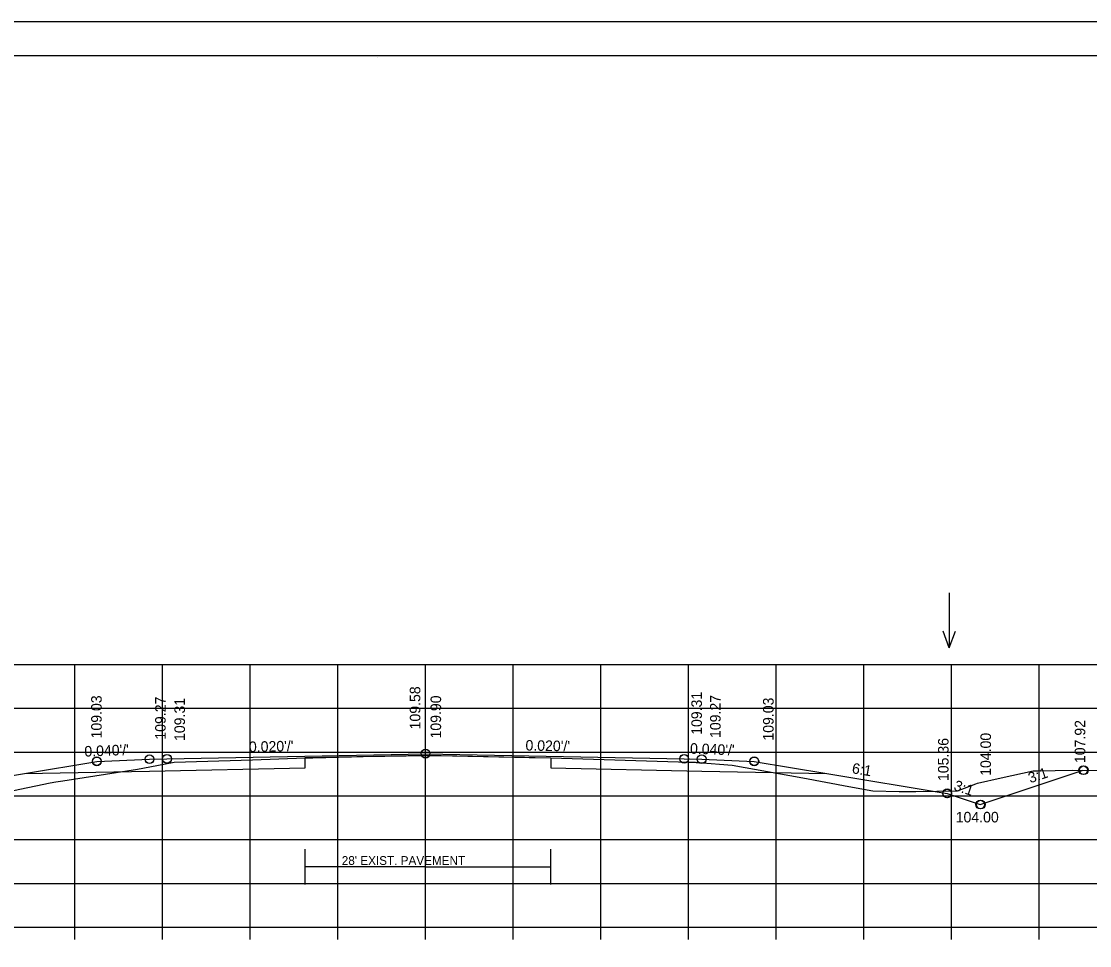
# Model space of a CAD drawing. Extents: x 1175611 to 1176402, y -433344 to -416213.
# Drawn here: x 1175734.9 to 1175856.7, y -433235.6 to -433130.2 of the extents above; entities that cross this region are included whole.
import ezdxf

# ---------------------------------------------------------------- set-up
doc = ezdxf.new("R2010")
doc.units = 0
for name, color, linetype in [('R_Alt Surface', 7, 'Continuous'), ('R_Axis', 7, 'Continuous'), ('R_Border', 7, 'Continuous'), ('R_Draft', 7, 'Continuous'), ('R_Exist Surface', 7, 'Continuous'), ('R_Fin Surface', 7, 'Continuous'), ('R_Grid', 7, 'Continuous'), ('R_No Plot', 7, 'Continuous'), ('R_Water Annot', 7, 'Continuous'), ('R_Xsect Elev', 7, 'Continuous'), ('R_Xsect Slope', 7, 'Continuous')]:
    doc.layers.add(name, color=color, linetype=linetype)

msp = doc.modelspace()

# ---------------------------------------------------------------- linework, layer by layer
at = {"layer": 'R_Alt Surface'}
msp.add_lwpolyline([(1175735.2, -433216), (1175749.47, -433215.72), (1175767.25, -433215.36), (1175767.25, -433214.19), (1175780.97, -433213.92), (1175795.26, -433214.21), (1175795.26, -433215.37), (1175812.47, -433215.72), (1175826.75, -433216)], dxfattribs=at)
at = {"layer": 'R_Axis'}
for p, q in [((1175640.97, -433233.55), (1175920.97, -433233.55)), ((1175740.97, -433234.95), (1175740.97, -433233.55)), ((1175750.97, -433234.95), (1175750.97, -433233.55)), ((1175760.97, -433234.95), (1175760.97, -433233.55)), ((1175770.97, -433234.95), (1175770.97, -433233.55)), ((1175780.97, -433234.95), (1175780.97, -433233.55)), ((1175790.97, -433234.95), (1175790.97, -433233.55)), ((1175800.97, -433234.95), (1175800.97, -433233.55)), ((1175810.97, -433234.95), (1175810.97, -433233.55)), ((1175820.97, -433234.95), (1175820.97, -433233.55)), ((1175830.97, -433234.95), (1175830.97, -433233.55)), ((1175840.97, -433234.95), (1175840.97, -433233.55)), ((1175850.97, -433234.95), (1175850.97, -433233.55))]:
    msp.add_line(p, q, dxfattribs=at)
at = {"layer": 'R_Border'}
for p, q in [((1175622.97, -433134.09), (1175939.15, -433134.09)), ((1175775.49, -433134.35), (1175775.49, -433134.35)), ((1175775.49, -433134.35), (1175775.49, -433134.35))]:
    msp.add_line(p, q, dxfattribs=at)
at = {"layer": 'R_Draft'}
for q in [(1175767.25, -433226.65), (1175795.26, -433226.65)]:
    msp.add_line((1175780.9, -433226.65), q, dxfattribs=at)
for points in [[(1175767.25, -433228.65), (1175767.25, -433224.65)], [(1175795.26, -433228.65), (1175795.26, -433224.65)]]:
    msp.add_lwpolyline(points, dxfattribs=at)
at = {"layer": 'R_Exist Surface'}
msp.add_lwpolyline([(1175729.72, -433218.82), (1175738.16, -433217.08), (1175738.78, -433216.96), (1175739.58, -433216.83), (1175748.11, -433215.51), (1175749.53, -433215.25), (1175752.27, -433214.72), (1175761.21, -433214.43), (1175767.25, -433214.22), (1175768.12, -433214.2), (1175772.5, -433214.09), (1175773.84, -433214.07), (1175781.24, -433213.96), (1175781.35, -433213.96), (1175781.45, -433213.96), (1175781.86, -433213.95), (1175782.27, -433213.96), (1175791.13, -433214.13), (1175792.25, -433214.15), (1175792.79, -433214.16), (1175795.26, -433214.23), (1175811.04, -433214.71), (1175811.4, -433214.72), (1175811.73, -433214.72), (1175811.85, -433214.74), (1175812.1, -433214.75), (1175815.94, -433215.05), (1175819.96, -433215.76), (1175824.01, -433216.48), (1175829.26, -433217.48), (1175832.01, -433217.99), (1175835.01, -433218.05), (1175836.39, -433218.07), (1175836.89, -433218.07), (1175841.65, -433217.97), (1175843.73, -433217.19), (1175843.92, -433217.11), (1175846.65, -433216.51), (1175850.3, -433215.71), (1175850.82, -433215.69), (1175854.78, -433215.62), (1175862.52, -433215.68)], dxfattribs=at)
at = {"layer": 'R_Fin Surface'}
msp.add_lwpolyline([(1175709.02, -433216.06), (1175718.59, -433219.25), (1175721.47, -433218.29), (1175735.2, -433216), (1175743.47, -433214.62), (1175749.47, -433214.38), (1175751.47, -433214.34), (1175780.97, -433213.75), (1175810.47, -433214.34), (1175812.47, -433214.38), (1175818.47, -433214.62), (1175826.75, -433216), (1175840.47, -433218.29), (1175844.24, -433219.55), (1175855.98, -433215.63)], dxfattribs=at)
msp.add_lwpolyline([(1175709.02, -433216.06), (1175718.59, -433219.25), (1175721.47, -433218.29), (1175735.2, -433216), (1175743.47, -433214.62), (1175749.47, -433214.38), (1175751.47, -433214.34), (1175780.97, -433213.75), (1175810.47, -433214.34), (1175812.47, -433214.38), (1175818.47, -433214.62), (1175826.75, -433216), (1175840.47, -433218.29), (1175844.24, -433219.55), (1175855.98, -433215.63)], dxfattribs=at)
at = {"layer": 'R_Grid'}
for p, q in [((1175640.97, -433203.55), (1175920.97, -433203.55)), ((1175740.97, -433233.55), (1175740.97, -433203.55)), ((1175750.97, -433233.55), (1175750.97, -433203.55)), ((1175760.97, -433233.55), (1175760.97, -433203.55)), ((1175770.97, -433233.55), (1175770.97, -433203.55)), ((1175780.97, -433233.55), (1175780.97, -433203.55)), ((1175790.97, -433233.55), (1175790.97, -433203.55)), ((1175800.97, -433233.55), (1175800.97, -433203.55)), ((1175810.97, -433233.55), (1175810.97, -433203.55)), ((1175820.97, -433233.55), (1175820.97, -433203.55)), ((1175830.97, -433233.55), (1175830.97, -433203.55)), ((1175840.97, -433233.55), (1175840.97, -433203.55)), ((1175850.97, -433233.55), (1175850.97, -433203.55)), ((1175640.97, -433208.55), (1175920.97, -433208.55)), ((1175640.97, -433213.55), (1175920.97, -433213.55)), ((1175640.97, -433218.55), (1175920.97, -433218.55)), ((1175640.97, -433223.55), (1175920.97, -433223.55)), ((1175640.97, -433228.55), (1175920.97, -433228.55)), ((1175640.97, -433233.55), (1175920.97, -433233.55))]:
    msp.add_line(p, q, dxfattribs=at)
at = {"layer": 'R_No Plot'}
msp.add_line((1175610.57, -433130.2), (1175943.91, -433130.2), dxfattribs=at)
msp.add_lwpolyline([(1175610.57, -433130.2), (1175943.91, -433130.2), (1175943.91, -433343.53), (1175610.57, -433343.53)], close=True, dxfattribs=at)
for centre in [(1175743.47, -433214.6), (1175743.47, -433214.62), (1175749.47, -433214.36), (1175749.47, -433214.38), (1175751.47, -433214.32), (1175751.47, -433214.34), (1175780.97, -433213.73), (1175780.97, -433213.75), (1175810.47, -433214.32), (1175810.47, -433214.34), (1175812.47, -433214.36), (1175812.47, -433214.38), (1175818.47, -433214.6), (1175818.47, -433214.62), (1175855.98, -433215.63), (1175855.98, -433215.63), (1175856.06, -433215.63), (1175840.47, -433218.26), (1175840.47, -433218.29), (1175844.24, -433219.55), (1175844.24, -433219.55), (1175844.32, -433219.55)]:
    msp.add_circle(centre, 0.5, dxfattribs=at)
at = {"layer": 'R_Water Annot'}
for p, q in [((1175840.72, -433195.39), (1175840.72, -433201.67)), ((1175840.72, -433201.67), (1175840.02, -433199.75)), ((1175840.72, -433201.67), (1175841.42, -433199.75))]:
    msp.add_line(p, q, dxfattribs=at)

# ---------------------------------------------------------------- texts
at = {"layer": 'R_Draft'}
msp.add_text("28' EXIST. PAVEMENT", height=1, dxfattribs=at).set_placement((1175771.41, -433226.43))
at = {"layer": 'R_Xsect Elev'}
for s, p in [('109.58', (1175780.37, -433210.97)), ('109.31', (1175812.49, -433211.59)), ('109.03', (1175744.02, -433212)), ('109.27', (1175751.32, -433212.14)), ('109.31', (1175753.52, -433212.29)), ('109.90', (1175782.74, -433212.01)), ('109.27', (1175814.63, -433211.95)), ('109.03', (1175820.67, -433212.25)), ('107.92', (1175856.23, -433214.81)), ('104.00', (1175845.47, -433216.27)), ('105.36', (1175840.63, -433216.86))]:
    msp.add_text(s, height=1.2, rotation=90, dxfattribs=at).set_placement(p)
msp.add_text('104.00', height=1.2, dxfattribs=at).set_placement((1175841.45, -433221.58))
at = {"layer": 'R_Xsect Slope'}
for s, rotation, p in [("0.040'/'", 2.2906, (1175742.07, -433214.08)), ("0.020'/'", 1.1458, (1175760.83, -433213.56)), ("0.020'/'", 358.8542, (1175792.36, -433213.38)), ("0.040'/'", 357.7094, (1175811.12, -433213.73)), ('6:1', 350.5377, (1175829.55, -433215.96)), ('3:1', 18.4349, (1175849.95, -433217.12)), ('3:1', 341.5651, (1175841.14, -433217.86))]:
    msp.add_text(s, height=1.2, rotation=rotation, dxfattribs=at).set_placement(p)

doc.saveas('drawing.dxf')
